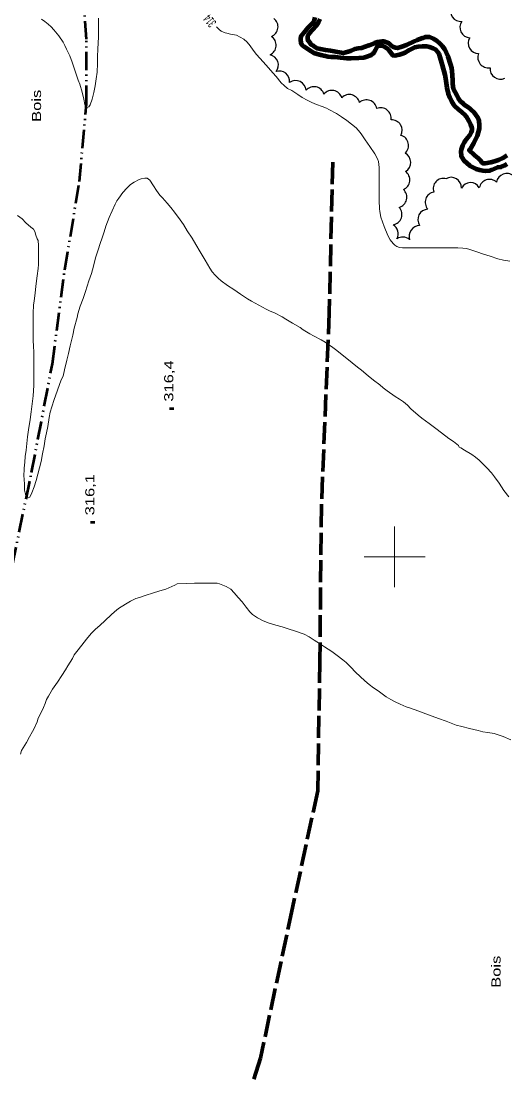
# Model space of a CAD drawing. Extents: x 240591 to 242335, y 5323482 to 5326937.
# Drawn here: x 240877.4 to 241036.2, y 5323830.7 to 5324175.8 of the extents above; entities that cross this region are included whole.
import ezdxf

# ---------------------------------------------------------------- set-up
doc = ezdxf.new("R2010")
doc.units = 0
doc.header["$LTSCALE"] = 1.2
doc.linetypes.add('DASH_DOUBLE_DOT', pattern=[9.2, 5, -1.2, 0.3, -1.2, 0.3, -1.2])
doc.linetypes.add('LONG_DASHED', pattern=[7.5, 6, -1.5])
for name, color, linetype, lineweight in [('2', 7, 'Continuous', 13), ('22', 7, 'LONG_DASHED', 70), ('3', 7, 'Continuous', 140), ('4', 7, 'DASH_DOUBLE_DOT', 53), ('44', 7, 'Continuous', 25), ('61', 7, 'Continuous', 13)]:
    doc.layers.add(name, color=color, linetype=linetype, lineweight=lineweight)

msp = doc.modelspace()

# ---------------------------------------------------------------- linework, layer by layer
at = {"layer": '2', "linetype": 'LONG_DASHED'}
for points in [[(240902.8, 5324176.7), (240902.8, 5324175.2), (240902.8, 5324172.7), (240902.8, 5324170.3), (240902.7, 5324168.9), (240902.6, 5324166.3), (240902.5, 5324164.4), (240902.5, 5324161.9), (240902.4, 5324159), (240902.1, 5324156.8), (240901.8, 5324154.5), (240901.3, 5324152.3), (240900.8, 5324150.2), (240900.1, 5324148.3), (240899.7, 5324147.6), (240899.1, 5324147.4), (240898.8, 5324147.7), (240898.4, 5324148.4), (240898, 5324150.1), (240897.5, 5324152.4), (240896.7, 5324155.1), (240896.2, 5324156.4), (240895.2, 5324159.3), (240894.2, 5324162.3), (240893.4, 5324164.4), (240892.4, 5324166.6), (240891.8, 5324167.8), (240891.2, 5324168.9), (240889.8, 5324170.9), (240888.2, 5324172.9), (240887.3, 5324173.9), (240886.3, 5324174.8), (240885.2, 5324175.6), (240884.1, 5324176.4)], [(240941.6, 5324173.9), (240942.5, 5324173), (240943.1, 5324172.5), (240944.4, 5324171.9), (240945, 5324171.8), (240946.2, 5324171.5), (240948.1, 5324171.1), (240949.3, 5324170.5), (240950.5, 5324169.8), (240951.6, 5324168.8), (240952.6, 5324167.6), (240953.6, 5324166.2), (240954.7, 5324164.8), (240955.8, 5324163.6), (240957.9, 5324161.3), (240960.1, 5324158.8), (240961.1, 5324157.6), (240962.8, 5324155.5), (240963.8, 5324154.6), (240964.9, 5324153.7), (240966.3, 5324153), (240968.3, 5324151.7), (240969.7, 5324150.7), (240971.3, 5324149.8), (240972.9, 5324149.1), (240974.4, 5324148.4), (240976.2, 5324147.7)], [(240919.7, 5324123.6), (240918.8, 5324124.2), (240918, 5324124.2), (240916.8, 5324124), (240916.2, 5324123.8), (240914.5, 5324122.9), (240913.4, 5324122.2), (240912.2, 5324121), (240910.8, 5324119.5), (240909.5, 5324117.7), (240908.9, 5324116.8), (240908.3, 5324115.7), (240907.3, 5324113.5), (240906.4, 5324111.3), (240905.3, 5324108.5), (240904.7, 5324106.6), (240904.1, 5324104.7), (240903.4, 5324102.8), (240902.7, 5324100.7), (240901.9, 5324098.1), (240901.2, 5324095.4), (240900.5, 5324092.9), (240899.7, 5324090.6), (240898.6, 5324087), (240897.8, 5324084.7), (240896.8, 5324082.2), (240896.1, 5324079.7), (240895.8, 5324078.5), (240894.9, 5324075), (240894.4, 5324072.7), (240893.6, 5324069.2), (240893, 5324066.7), (240892.5, 5324064.5), (240891.7, 5324061.4), (240891.2, 5324059.3), (240890.7, 5324058.3), (240890.2, 5324056.9), (240889.3, 5324054.4), (240888.3, 5324051.6), (240887.5, 5324049.2), (240887, 5324047.5), (240886.7, 5324045.7), (240886.2, 5324042.8), (240885.8, 5324040.7), (240885.4, 5324038.7), (240885, 5324036.4), (240884.5, 5324033.8), (240884, 5324031.3), (240883.5, 5324029.2), (240882.9, 5324027.1), (240882.4, 5324025), (240881.7, 5324023), (240881, 5324021), (240880.3, 5324019.6), (240879.8, 5324019.3), (240879.3, 5324019.5), (240879, 5324020), (240878.9, 5324020.5), (240878.6, 5324021.9), (240878.6, 5324023.4), (240878.4, 5324025.8), (240878.3, 5324026.2)], [(240919.7, 5324123.6), (240920.9, 5324121.7), (240921.9, 5324120.2), (240923, 5324118.7), (240923.8, 5324117.8), (240925.4, 5324116), (240926.6, 5324114.6), (240927.8, 5324113.1), (240929.7, 5324110.6), (240930.7, 5324109), (240932, 5324107), (240933.6, 5324104.5), (240934.8, 5324102.5), (240936.2, 5324100.1), (240937.8, 5324097.3), (240939.4, 5324094.7), (240940.2, 5324093.5), (240941.1, 5324092.4), (240942.1, 5324091.4), (240943.1, 5324090.5), (240945.2, 5324089), (240947.3, 5324087.7), (240949.5, 5324086.2), (240951.8, 5324084.6), (240953.1, 5324083.9), (240955.5, 5324082.6), (240957.9, 5324081.2), (240959.2, 5324080.6), (240960.6, 5324080), (240963.1, 5324078.7), (240964.3, 5324078), (240966.5, 5324076.7), (240969, 5324075.2), (240970, 5324074.5), (240972.2, 5324073.2), (240973.4, 5324072.5), (240975.9, 5324071.2), (240977.2, 5324070.4), (240979.8, 5324068.7), (240981.1, 5324067.7), (240982.8, 5324066.3), (240984.9, 5324064.6), (240986.1, 5324063.6), (240987.8, 5324062.2), (240989.2, 5324061.2), (240991.4, 5324059.4), (240993.1, 5324058), (240995.2, 5324056.4), (240996.3, 5324055.4), (240997.6, 5324054.5), (241000.2, 5324052.6), (241001.6, 5324051.7), (241002.9, 5324050.8), (241004.2, 5324049.8), (241005.4, 5324048.6), (241007.8, 5324046.5), (241009, 5324045.5), (241011.4, 5324043.7), (241013.6, 5324042.1)], [(240881.5, 5324107.5), (240880.6, 5324108.2), (240879, 5324109.6), (240877.8, 5324110.9), (240876.3, 5324112)], [(241024.7, 5324100.8), (241027.3, 5324099.9), (241028.9, 5324099.4), (241031.4, 5324098.6), (241033.9, 5324097.8), (241035.8, 5324097.3), (241037.8, 5324097)], [(241013.6, 5324042.1), (241015.4, 5324040.7), (241017.8, 5324038.8), (241019.3, 5324037.8), (241021, 5324036.5), (241021.2, 5324036), (241021.8, 5324035.8), (241023, 5324035), (241025.4, 5324033.6), (241026.6, 5324032.7), (241027.8, 5324031.7), (241029.4, 5324030.1), (241030.3, 5324029.2), (241031.8, 5324027.5), (241032.8, 5324026.2), (241034.3, 5324024.2), (241035.9, 5324021.8), (241037.5, 5324019.7)], [(240946.3, 5323989.4), (240944.7, 5323990.3), (240942.6, 5323991.1), (240941.8, 5323991.3), (240940.4, 5323991.3), (240939.1, 5323991.3), (240936.5, 5323991.3), (240934.3, 5323991.3), (240931.8, 5323991.2), (240928.7, 5323991.1), (240927.9, 5323990.7), (240926.9, 5323990.3), (240924.9, 5323989.4), (240923.7, 5323989.1), (240921.2, 5323988.3), (240917.8, 5323987.2), (240916.3, 5323986.7), (240915.1, 5323986.3), (240914.4, 5323986), (240913.4, 5323985.5), (240911.7, 5323984.5), (240909.4, 5323983), (240908.1, 5323982), (240907, 5323981), (240905, 5323979.1), (240903.3, 5323977.5), (240901.9, 5323976.3), (240900.4, 5323974.8), (240898.9, 5323973), (240897.4, 5323971), (240895.7, 5323968.9), (240894.9, 5323967.8), (240894.3, 5323966.6), (240892.8, 5323964.2), (240892, 5323962.9), (240890.8, 5323961.1), (240889.4, 5323958.9), (240887.7, 5323956.6), (240886.4, 5323954.3), (240885.8, 5323953.2), (240885.3, 5323951.9), (240884.8, 5323950.6), (240884.2, 5323949.4), (240883.1, 5323947.1), (240882.7, 5323945.9), (240881.7, 5323943.7), (240881.2, 5323942.7), (240880.2, 5323940.9), (240879.2, 5323939.1), (240877.6, 5323936.5), (240877.2, 5323935.3)], [(240946.3, 5323989.4), (240947.4, 5323988.2), (240948.7, 5323986.7), (240950, 5323985.2), (240951.3, 5323983.5), (240952.5, 5323982), (240953.4, 5323981.1), (240955, 5323980), (240956.9, 5323979), (240958.9, 5323978.2), (240961, 5323977.6), (240963.1, 5323977), (240965.1, 5323976.4), (240967.5, 5323975.6), (240970.3, 5323974.6), (240972, 5323973.7), (240973.6, 5323972.7), (240975.4, 5323971.6), (240977, 5323970.5), (240979.4, 5323968.9)], [(240979.4, 5323968.9), (240981.2, 5323967.6), (240983, 5323966.2), (240984.1, 5323965.3), (240985.7, 5323963.8), (240987.2, 5323962.2), (240988.7, 5323960.7), (240990.2, 5323959.3), (240991.7, 5323958.1), (240993.1, 5323957), (240994.6, 5323956), (240997.3, 5323954.1), (240998.8, 5323953.2), (241000.2, 5323952.4), (241001.8, 5323951.7), (241003.8, 5323950.8), (241004.9, 5323950.4), (241008, 5323949.4), (241011.1, 5323948.2), (241014.4, 5323947), (241016.9, 5323946.1), (241020.2, 5323944.8), (241022.1, 5323944.3), (241024.6, 5323943.7), (241027.4, 5323943), (241029, 5323942.6), (241030.6, 5323942.4), (241032.7, 5323942), (241033.7, 5323941.7), (241035.6, 5323941.1), (241038.2, 5323940)]]:
    msp.add_lwpolyline(points, dxfattribs=at)
at = {"layer": '2'}
for points in [[(240976.2, 5324147.7), (240977.7, 5324147.2), (240978.4, 5324146.8), (240980.9, 5324145.4), (240982.6, 5324144.4), (240984.3, 5324143.2), (240985.9, 5324142), (240987.4, 5324140.7), (240988.7, 5324139.2), (240989.3, 5324138.4), (240990.4, 5324136.8), (240991.9, 5324134.6), (240993.5, 5324132.2), (240994.4, 5324130.6), (240994.7, 5324129.7), (240994.9, 5324128.7), (240995, 5324127.7), (240995, 5324125.8), (240995, 5324122.6), (240995, 5324119.4), (240995, 5324116.9), (240995.1, 5324114.2), (240995.2, 5324113.3), (240995.5, 5324111.4), (240996, 5324109.9), (240996.6, 5324108.4), (240997.8, 5324105.4), (240998.6, 5324104), (240999.5, 5324102.8), (241000.1, 5324102.2), (241000.8, 5324101.8), (241001.6, 5324101.5), (241002.6, 5324101.4), (241003.6, 5324101.4), (241006.3, 5324101.4), (241009, 5324101.4), (241012, 5324101.4), (241015, 5324101.4), (241018, 5324101.4), (241020.8, 5324101.4), (241022.4, 5324101.3), (241023.6, 5324101.1), (241024.7, 5324100.8)], [(240878.3, 5324026.2), (240878.5, 5324029.1), (240878.7, 5324031), (240878.8, 5324032.9), (240879.1, 5324035), (240879.3, 5324037.2), (240879.5, 5324039.4), (240879.9, 5324041.7), (240880.4, 5324045.1), (240880.8, 5324047.6), (240881.1, 5324050.2), (240881.4, 5324052.8), (240881.6, 5324056.2), (240881.6, 5324057.4), (240881.6, 5324060.9), (240881.6, 5324064.7), (240881.6, 5324067.5), (240881.5, 5324068.8), (240881.4, 5324071.3), (240881.4, 5324073.7), (240881.4, 5324077.3), (240881.4, 5324079.9), (240881.5, 5324082.6), (240881.7, 5324084), (240882.1, 5324086.5), (240882.3, 5324088.8), (240882.7, 5324092.2), (240883.1, 5324094.6), (240883.2, 5324095.9), (240883.2, 5324097.2), (240883.2, 5324099.5), (240883.2, 5324102.1), (240883, 5324103.8), (240882.7, 5324104.3), (240882.3, 5324105.5), (240881.9, 5324106.7), (240881.5, 5324107.5)]]:
    msp.add_lwpolyline(points, dxfattribs=at)
at = {"layer": '22'}
msp.add_lwpolyline([(240979.7, 5324129.5), (240978.6, 5324080.2), (240976, 5324016.9), (240975.5, 5323965.8), (240974.8, 5323923.2), (240966.5, 5323884.8), (240956, 5323835.5), (240938, 5323780), (240924, 5323745.3), (240912.3, 5323717.6), (240916.6, 5323692.3), (240928.4, 5323654.8), (240927.6, 5323605.5), (240922.5, 5323559.8), (240914.2, 5323517), (240905.4, 5323502.5)], dxfattribs=at)
at = {"layer": '3'}
for p, q in [((240926.9, 5324048.2), (240926.9, 5324049)), ((240901, 5324010.9), (240901, 5324011.7))]:
    msp.add_line(p, q, dxfattribs=at)
at = {"layer": '4'}
msp.add_lwpolyline([(240813.8, 5323894.5), (240837.9, 5323894.8), (240853.6, 5323903.1), (240863.6, 5323934.4), (240867.4, 5323966.2), (240874.6, 5323997.3), (240880.9, 5324027.7), (240887.7, 5324063.3), (240891.8, 5324094.2), (240896.6, 5324123.1), (240898.9, 5324148.6), (240898.9, 5324169.8), (240897.6, 5324189.2), (240897.7, 5324201.4)], dxfattribs=at)
at = {"layer": '4', "linetype": 'Continuous', "lineweight": 90}
for points in [[(240973.8, 5324176.9), (240973.5, 5324175.6), (240973.2, 5324175.2), (240972.7, 5324174.8), (240971.5, 5324173.5), (240970.7, 5324172.5), (240969.2, 5324170.7), (240969.1, 5324170), (240969.1, 5324169.5), (240969.2, 5324168.7), (240969.5, 5324168.2), (240969.9, 5324167.7), (240970.3, 5324167.4), (240971.4, 5324166.7), (240972.6, 5324165.9), (240973.5, 5324165.4), (240974.6, 5324165), (240975.8, 5324164.7), (240978.1, 5324164.1), (240979.2, 5324164), (240980.5, 5324164), (240982.3, 5324163.8), (240984.3, 5324163.6), (240985.8, 5324163.6), (240988.3, 5324163.7), (240989.9, 5324163.8), (240990.6, 5324164), (240992.4, 5324164.7), (240992.9, 5324165.1), (240993.3, 5324165.5), (240993.7, 5324166.2), (240994.3, 5324167.4), (240994.9, 5324167.8), (240995.4, 5324167.8), (240996.2, 5324167.6), (240996.8, 5324167.3), (240997.9, 5324166.5), (240998.3, 5324165.9), (240999.3, 5324164.6), (241000.1, 5324164.5), (241000.6, 5324164.6)], [(241036.8, 5324131.7), (241035.5, 5324130.8), (241034.1, 5324130.1), (241032.8, 5324129.7), (241031.6, 5324129.4), (241029.7, 5324129), (241029.1, 5324129), (241028.7, 5324129.4), (241028.3, 5324129.9), (241027.4, 5324130.8), (241026.3, 5324131.7), (241024.5, 5324133.4), (241024.9, 5324133.9), (241026, 5324135.7), (241026.7, 5324137), (241027.2, 5324138.1), (241027.6, 5324139.3), (241027.9, 5324140.5), (241027.9, 5324141.7), (241027.8, 5324142.9), (241027.6, 5324143.5), (241027.2, 5324144.2), (241026.1, 5324145.8), (241025.2, 5324146.7), (241024.6, 5324147.2), (241023.4, 5324148), (241022.6, 5324148.6), (241021.8, 5324149.3), (241021, 5324150.4), (241020.5, 5324151.4), (241019.4, 5324153.5), (241019.2, 5324154.3), (241019.1, 5324155.3), (241019.1, 5324156.4), (241018.9, 5324159.3), (241018.8, 5324160.3), (241018.5, 5324161.4), (241017.6, 5324164.2), (241017.1, 5324165.4), (241016.5, 5324166.5), (241015.7, 5324167.5), (241014.9, 5324168.4), (241013.9, 5324169.3), (241012.8, 5324169.9), (241011.6, 5324170.5), (241011, 5324170.5), (241009.9, 5324170.5), (241009.2, 5324170.2), (241007.4, 5324169.5), (241006.4, 5324169.1), (241003.9, 5324167.9), (241002.4, 5324167.3), (241001, 5324166.9), (241000.3, 5324167), (240999.7, 5324167.2), (240999, 5324167.7), (240998.2, 5324168.4), (240996.5, 5324169.1), (240995.9, 5324169.1), (240994.4, 5324168.9), (240993.4, 5324168.5), (240991.6, 5324167.8), (240989.2, 5324166.9), (240988.1, 5324166.8), (240987, 5324166.5), (240985.5, 5324165.9), (240983.3, 5324165.2), (240982.6, 5324165.4), (240981.3, 5324165.6), (240980.2, 5324165.8), (240979, 5324166), (240977.3, 5324166.2), (240975.7, 5324166.5), (240974.6, 5324166.8), (240973.6, 5324167.4), (240973.3, 5324167.8), (240972.8, 5324168), (240972.4, 5324168.4), (240971.8, 5324169.2), (240971.6, 5324169.8), (240971.6, 5324170.3), (240971.6, 5324170.8), (240971.9, 5324171.5), (240972.8, 5324172.6), (240973.2, 5324173), (240974.4, 5324174.3), (240975, 5324175.3), (240975.6, 5324176.5)], [(241000.6, 5324164.6), (241001.6, 5324164.8), (241002.6, 5324165.1), (241003.5, 5324165.5), (241004.9, 5324166.3), (241006.7, 5324167.2), (241007.8, 5324167.4), (241009.2, 5324167.5), (241010.5, 5324167.5), (241011.5, 5324167.3), (241012.7, 5324166.9), (241013.3, 5324166.5), (241014.3, 5324165.5), (241014.5, 5324165), (241014.9, 5324163.9), (241015.4, 5324162.1), (241016.2, 5324159.3), (241016.5, 5324158.1), (241016.7, 5324156.9), (241017.2, 5324153.9), (241017.6, 5324152), (241018.1, 5324150.7), (241018.7, 5324149.5), (241019.4, 5324148.4), (241019.8, 5324147.9), (241020.9, 5324146.9), (241022.1, 5324145.9), (241023.1, 5324145), (241023.5, 5324144.5), (241024.4, 5324142.9), (241024.9, 5324141.8), (241025.4, 5324140.6), (241025.4, 5324140), (241025.2, 5324139.3), (241024.6, 5324138.2), (241024.1, 5324137.6), (241023.2, 5324136.5), (241022.8, 5324136), (241022.3, 5324134.9), (241021.9, 5324133.6), (241021.8, 5324133), (241021.9, 5324131.7), (241022.1, 5324131.1), (241022.9, 5324129.9), (241023.7, 5324129.1), (241024.6, 5324128.4), (241025.5, 5324127.9), (241026.8, 5324127.3), (241027.9, 5324127), (241029, 5324126.7), (241030, 5324126.6), (241031.4, 5324126.7), (241031.9, 5324127), (241033.9, 5324127.8), (241035, 5324128), (241036.1, 5324128.4), (241037, 5324128.9)]]:
    msp.add_lwpolyline(points, dxfattribs=at)
at = {"layer": '44'}
for centre, radius, start, end in [((240958.343, 5324173.91), 3.43, 291.13063, 52.74445), ((241030.749, 5324163.831), 3.404, 158.10908, 280.17196), ((241034.757, 5324160.118), 3.426, 173.93552, 295.6569), ((241001.603, 5324123.657), 3.432, 292.21349, 54.19952), ((241018.611, 5324121.132), 3.372, 357.75715, 121.07684), ((241036.821, 5324122.382), 3.392, 48.92847, 171.05422), ((241000.606, 5324117.931), 3.429, 286.32003, 48.02055), ((241013.461, 5324116.325), 3.418, 100.13244, 221.72245), ((240998.975, 5324112.346), 3.464, 279.56303, 41.47293), ((241011.051, 5324110.647), 3.405, 92.37531, 214.06379), ((241008.522, 5324104.983), 3.768, 94.44996, 194.36384)]:
    msp.add_arc(centre, radius, start, end, dxfattribs=at)
for centre, major_axis, ratio, start_param, end_param in [((241021.749, 5324179.057), (-3.273, -0.936), 0.999961, 5.5441299, 7.6757739), ((241024.883, 5324173.708), (-3.206, -1.175), 0.99959, 5.3193471, 7.4461961), ((240957.704, 5324167.821), (-2.871, 1.903), 0.999984, 2.5924495, 4.7217471), ((241027.587, 5324168.507), (3.407, -0.028), 0.999983, 2.5956106, 4.7215758), ((240958.481, 5324161.366), (3.101, 1.411), 0.997953, 5.1684457, 7.2267868), ((240962.179, 5324155.985), (-2.794, 1.942), 0.999937, 3.6356247, 5.6397678), ((240967.571, 5324152.823), (1.451, 3.106), 0.999994, 5.2214315, 7.3468363), ((240973.565, 5324150.814), (0.729, 3.345), 0.99986, 5.222202, 7.3492085), ((240979.448, 5324149.594), (-3.233, -1.124), 0.999995, 3.1145418, 5.2444744), ((240985.16, 5324148.23), (1.392, 3.135), 0.999828, 5.3713897, 7.4967705), ((240990.788, 5324146.481), (1.122, 3.259), 0.999994, 5.2214908, 7.3446067), ((240995.467, 5324143.916), (2.151, 2.665), 0.999978, 5.2166377, 7.3476276), ((240999.083, 5324139.888), (2.888, 1.87), 0.999994, 5.219021, 7.3499593), ((241001.176, 5324134.968), (3.389, 0.57), 0.999129, 5.2846214, 7.4090599), ((241001.879, 5324129.402), (3.423, -0.238), 0.999493, 5.310477, 7.4347457), ((241016.049, 5324120.779), (-2.296, -2.467), 0.999937, 3.6338586, 5.7909194), ((241024.928, 5324119.431), (0.73, 3.259), 0.999924, 5.4562062, 7.5853876), ((241031.146, 5324120.441), (-0.248, 3.382), 0.999926, 5.4547371, 7.5854124), ((240997.826, 5324105.999), (0.125, 3.398), 0.999984, 4.2363194, 5.7880955), ((241002.636, 5324101.511), (-3.393, 0.197), 0.999984, 4.0482837, 5.350454)]:
    msp.add_ellipse(centre, major_axis=major_axis, ratio=ratio, start_param=start_param, end_param=end_param, dxfattribs=at)
at = {"layer": '61'}
for points in [[(241000, 5324010), (241000, 5324000), (241000, 5323990)], [(240990, 5324000), (241000, 5324000), (241010, 5324000)]]:
    msp.add_lwpolyline(points, dxfattribs=at)

# ---------------------------------------------------------------- texts
at = {"layer": '2', "width": 0.45}
msp.add_text('314', height=3, rotation=129.181, dxfattribs=at).set_placement((240941.7, 5324175.3))
at = {"layer": '3', "width": 1.35}
for s, p in [('316,4', (240927.4, 5324050.9)), ('316,1', (240901.5, 5324013.6))]:
    msp.add_text(s, height=3, rotation=90, dxfattribs=at).set_placement(p)
at = {"layer": '44', "width": 1.35}
for p in [(240884, 5324142.7), (241034.8, 5323858.6)]:
    msp.add_text('Bois', height=3, rotation=90, dxfattribs=at).set_placement(p)

doc.saveas('drawing.dxf')
